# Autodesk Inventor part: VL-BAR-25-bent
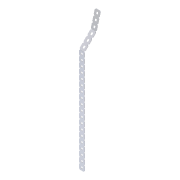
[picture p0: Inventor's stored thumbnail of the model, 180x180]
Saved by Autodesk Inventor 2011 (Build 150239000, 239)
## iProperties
Created: 2007-12
Part Number: VL-BAR-25-bent
Document SubType Name: Modeling
Density: 1 g/cm^3
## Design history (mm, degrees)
feature "Base1"
sketch "Sketch1" dims "d5" = 25.4
  geometry: L1 (9.662, 0)-(0, 0) reference; L2 (9.662, 0)-(11.181, 1.519) reference; L3 (11.181, 1.519)-(11.181, 10.165) reference; L4 (11.181, 10.165)-(9.244, 12.102) reference; L5 (9.244, 12.282)-(11.181, 14.219) reference; L6 (11.181, 14.219)-(11.181, 22.865) reference; L7 (11.181, 22.865)-(9.244, 24.802) reference; L8 (9.244, 24.982)-(11.181, 26.919) reference; L9 (11.181, 26.919)-(11.181, 35.565) reference; L10 (11.181, 35.565)-(9.244, 37.502) reference; L11 (9.244, 37.682)-(11.181, 39.619) reference; L12 (11.181, 39.619)-(11.181, 48.265) reference; L13 (11.181, 48.265)-(9.244, 50.202) reference; L14 (9.244, 50.382)-(11.181, 52.319) reference; L15 (11.181, 52.319)-(11.181, 60.965) reference; L16 (11.181, 60.965)-(9.244, 62.902) reference; L17 (9.244, 63.082)-(11.181, 65.019) reference; L18 (11.181, 65.019)-(11.181, 73.665) reference; L19 (11.181, 73.665)-(9.244, 75.602) reference; L20 (9.244, 75.782)-(11.181, 77.719) reference; L21 (11.181, 77.719)-(11.181, 86.365) reference; L22 (11.181, 86.365)-(9.244, 88.302) reference; L23 (9.244, 88.482)-(11.181, 90.419) reference; L24 (11.181, 90.419)-(11.181, 99.065) reference; L25 (11.181, 99.065)-(9.244, 101.002) reference; L26 (9.244, 101.182)-(11.181, 103.119) reference; L27 (11.181, 103.119)-(11.181, 111.765) reference; L28 (11.181, 111.765)-(9.244, 113.702) reference; L29 (9.244, 113.882)-(11.181, 115.819) reference; L30 (11.181, 115.819)-(11.181, 124.465) reference; L31 (11.181, 124.465)-(9.244, 126.402) reference; L32 (9.244, 126.582)-(11.181, 128.519) reference; L33 (11.181, 128.519)-(11.181, 137.165) reference; L34 (11.181, 137.165)-(9.244, 139.102) reference; L35 (9.244, 139.282)-(11.181, 141.219) reference; L36 (11.181, 141.219)-(11.181, 149.865) reference; L37 (11.181, 149.865)-(9.244, 151.802) reference; L38 (9.244, 151.982)-(11.181, 153.919) reference; L39 (11.181, 153.919)-(11.181, 162.565) reference; L40 (11.181, 162.565)-(9.244, 164.502) reference; L41 (9.244, 164.682)-(11.181, 166.619) reference; L42 (11.181, 166.619)-(11.181, 175.265) reference; L43 (11.181, 175.265)-(9.244, 177.202) reference; L44 (9.244, 177.382)-(11.181, 179.319) reference; L45 (11.181, 179.319)-(11.181, 187.965) reference; L46 (11.181, 187.965)-(9.244, 189.902) reference; L47 (9.244, 190.082)-(11.181, 192.019) reference; L48 (11.181, 192.019)-(11.181, 200.665) reference; L49 (11.181, 200.665)-(9.244, 202.602) reference; L50 (9.244, 202.782)-(11.181, 204.719) reference; L51 (11.181, 204.719)-(11.181, 213.365) reference; L52 (11.181, 213.365)-(9.244, 215.302) reference; L53 (9.244, 215.482)-(11.181, 217.419) reference; L54 (11.181, 217.419)-(11.181, 226.065) reference; L55 (11.181, 226.065)-(9.244, 228.002) reference; L56 (9.244, 228.182)-(11.181, 230.119) reference; L57 (11.181, 230.119)-(11.181, 238.76) reference; L58 (11.181, 238.76)-(9.149, 240.792) reference; L59 (9.149, 240.792)-(0.513, 240.792) reference; L60 (0.513, 240.792)-(-1.519, 238.76) reference; L61 (-1.519, 238.76)-(-1.519, 230.119) reference; L62 (0.418, 228.182)-(-1.519, 230.119) reference; L63 (-1.519, 226.065)-(0.418, 228.002) reference; L64 (-1.519, 226.065)-(-1.519, 217.419) reference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; C1 r 2.311 at (4.831, 5.842); C2 r 2.311 at (4.831, 18.542); C3 r 2.311 at (4.831, 31.242); C4 r 2.311 at (4.831, 43.942); C5 r 2.311 at (4.831, 56.642); C6 r 2.311 at (4.831, 69.342); C7 r 2.311 at (4.831, 82.042); C8 r 2.311 at (4.831, 94.742); C9 r 2.311 at (4.831, 107.442); C10 r 2.311 at (4.831, 120.142); C11 r 2.311 at (4.831, 132.842); C12 r 2.311 at (4.831, 145.542); C13 r 2.311 at (4.831, 158.242); C14 r 2.311 at (4.831, 170.942); C15 r 2.311 at (4.831, 183.642); C16 r 2.311 at (4.831, 196.342); C17 r 2.311 at (4.831, 209.042); C18 r 2.311 at (4.831, 221.742); C19 r 2.311 at (4.831, 234.442); A1 r 0.127 centre (9.334, 12.192) between (9.244, 12.282) and (9.244, 12.102) reference; A2 r 0.127 centre (9.334, 24.892) between (9.244, 24.982) and (9.244, 24.802) reference; A3 r 0.127 centre (9.334, 37.592) between (9.244, 37.682) and (9.244, 37.502) reference; A4 r 0.127 centre (9.334, 50.292) between (9.244, 50.382) and (9.244, 50.202) reference; A5 r 0.127 centre (9.334, 62.992) between (9.244, 63.082) and (9.244, 62.902) reference; A6 r 0.127 centre (9.334, 75.692) between (9.244, 75.782) and (9.244, 75.602) reference; A7 r 0.127 centre (9.334, 88.392) between (9.244, 88.482) and (9.244, 88.302) reference; A8 r 0.127 centre (9.334, 101.092) between (9.244, 101.182) and (9.244, 101.002) reference; A9 r 0.127 centre (9.334, 113.792) between (9.244, 113.882) and (9.244, 113.702) reference; A10 r 0.127 centre (9.334, 126.492) between (9.244, 126.582) and (9.244, 126.402) reference; A11 r 0.127 centre (9.334, 139.192) between (9.244, 139.282) and (9.244, 139.102) reference; A12 r 0.127 centre (9.334, 151.892) between (9.244, 151.982) and (9.244, 151.802) reference; A13 r 0.127 centre (9.334, 164.592) between (9.244, 164.682) and (9.244, 164.502) reference; A14 r 0.127 centre (9.334, 177.292) between (9.244, 177.382) and (9.244, 177.202) reference; A15 r 0.127 centre (9.334, 189.992) between (9.244, 190.082) and (9.244, 189.902) reference; A16 r 0.127 centre (9.334, 202.692) between (9.244, 202.782) and (9.244, 202.602) reference; A17 r 0.127 centre (9.334, 215.392) between (9.244, 215.482) and (9.244, 215.302) reference; A18 r 0.127 centre (9.334, 228.092) between (9.244, 228.182) and (9.244, 228.002) reference; A19 r 0.127 centre (0.328, 228.092) between (0.418, 228.002) and (0.418, 228.182) reference; A20 r 0.127 centre (0.328, 215.392) between (0.418, 215.302) and (0.418, 215.482) reference; A21 r 0.127 centre (0.328, 202.692) between (0.418, 202.602) and (0.418, 202.782) reference; A22 r 0.127 centre (0.328, 189.992) between (0.418, 189.902) and (0.418, 190.082) reference; A23 r 0.127 centre (0.328, 177.292) between (0.418, 177.202) and (0.418, 177.382) reference; A24 r 0.127 centre (0.328, 164.592) between (0.418, 164.502) and (0.418, 164.682) reference; A25 r 0.127 centre (0.328, 151.892) between (0.418, 151.802) and (0.418, 151.982) reference; A26 r 0.127 centre (0.328, 139.192) between (0.418, 139.102) and (0.418, 139.282) reference; A27 r 0.127 centre (0.328, 126.492) between (0.418, 126.402) and (0.418, 126.582) reference; A28 r 0.127 centre (0.328, 113.792) between (0.418, 113.702) and (0.418, 113.882) reference; A29 r 0.127 centre (0.328, 101.092) between (0.418, 101.002) and (0.418, 101.182) reference; A30 r 0.127 centre (0.328, 88.392) between (0.418, 88.302) and (0.418, 88.482) reference; A31 r 0.127 centre (0.328, 75.692) between (0.418, 75.602) and (0.418, 75.782) reference; A32 r 0.127 centre (0.328, 62.992) between (0.418, 62.902) and (0.418, 63.082) reference; A33 r 0.127 centre (0.328, 50.292) between (0.418, 50.202) and (0.418, 50.382) reference; A34 r 0.127 centre (0.328, 37.592) between (0.418, 37.502) and (0.418, 37.682) reference; A35 r 0.127 centre (0.328, 24.892) between (0.418, 24.802) and (0.418, 24.982) reference; A36 r 0.127 centre (0.328, 12.192) between (0.418, 12.102) and (0.418, 12.282) reference; A37 r 0.508 centre (3.028, 7.645) between (3.028, 8.153) and (2.52, 7.645) reference; A38 r 0.508 centre (6.634, 7.645) between (7.142, 7.645) and (6.634, 8.153) reference; A39 r 0.508 centre (6.634, 4.039) between (6.634, 3.531) and (7.142, 4.039) reference; A40 r 0.508 centre (3.028, 4.039) between (2.52, 4.039) and (3.028, 3.531) reference; A41 r 0.508 centre (3.028, 20.345) between (3.028, 20.853) and (2.52, 20.345) reference; A42 r 0.508 centre (6.634, 20.345) between (7.142, 20.345) and (6.634, 20.853) reference; A43 r 0.508 centre (6.634, 16.739) between (6.634, 16.231) and (7.142, 16.739) reference; A44 r 0.508 centre (3.028, 16.739) between (2.52, 16.739) and (3.028, 16.231) reference; A45 r 0.508 centre (3.028, 33.045) between (3.028, 33.553) and (2.52, 33.045) reference; A46 r 0.508 centre (6.634, 33.045) between (7.142, 33.045) and (6.634, 33.553) reference; A47 r 0.508 centre (6.634, 29.439) between (6.634, 28.931) and (7.142, 29.439) reference; A48 r 0.508 centre (3.028, 29.439) between (2.52, 29.439) and (3.028, 28.931) reference; A49 r 0.508 centre (3.028, 45.745) between (3.028, 46.253) and (2.52, 45.745) reference; A50 r 0.508 centre (6.634, 45.745) between (7.142, 45.745) and (6.634, 46.253) reference; A51 r 0.508 centre (6.634, 42.139) between (6.634, 41.631) and (7.142, 42.139) reference; A52 r 0.508 centre (3.028, 42.139) between (2.52, 42.139) and (3.028, 41.631) reference; A53 r 0.508 centre (3.028, 58.445) between (3.028, 58.953) and (2.52, 58.445) reference; A54 r 0.508 centre (6.634, 58.445) between (7.142, 58.445) and (6.634, 58.953) reference; A55 r 0.508 centre (6.634, 54.839) between (6.634, 54.331) and (7.142, 54.839) reference; A56 r 0.508 centre (3.028, 54.839) between (2.52, 54.839) and (3.028, 54.331) reference; A57 r 0.508 centre (3.028, 71.145) between (3.028, 71.653) and (2.52, 71.145) reference; A58 r 0.508 centre (6.634, 71.145) between (7.142, 71.145) and (6.634, 71.653) reference; A59 r 0.508 centre (6.634, 67.539) between (6.634, 67.031) and (7.142, 67.539) reference; A60 r 0.508 centre (3.028, 67.539) between (2.52, 67.539) and (3.028, 67.031) reference; A61 r 0.508 centre (3.028, 83.845) between (3.028, 84.353) and (2.52, 83.845) reference; A62 r 0.508 centre (6.634, 83.845) between (7.142, 83.845) and (6.634, 84.353) reference; A63 r 0.508 centre (6.634, 80.239) between (6.634, 79.731) and (7.142, 80.239) reference; A64 r 0.508 centre (3.028, 80.239) between (2.52, 80.239) and (3.028, 79.731) reference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
  constraints: 19 centre point, 4 tangent, 1 vertical, 36 other
  dimensions: "d2" = 12.7 distance of C1.centre C2.centre
body "Solid1"
